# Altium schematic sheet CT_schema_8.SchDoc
size 368 x 245 mm
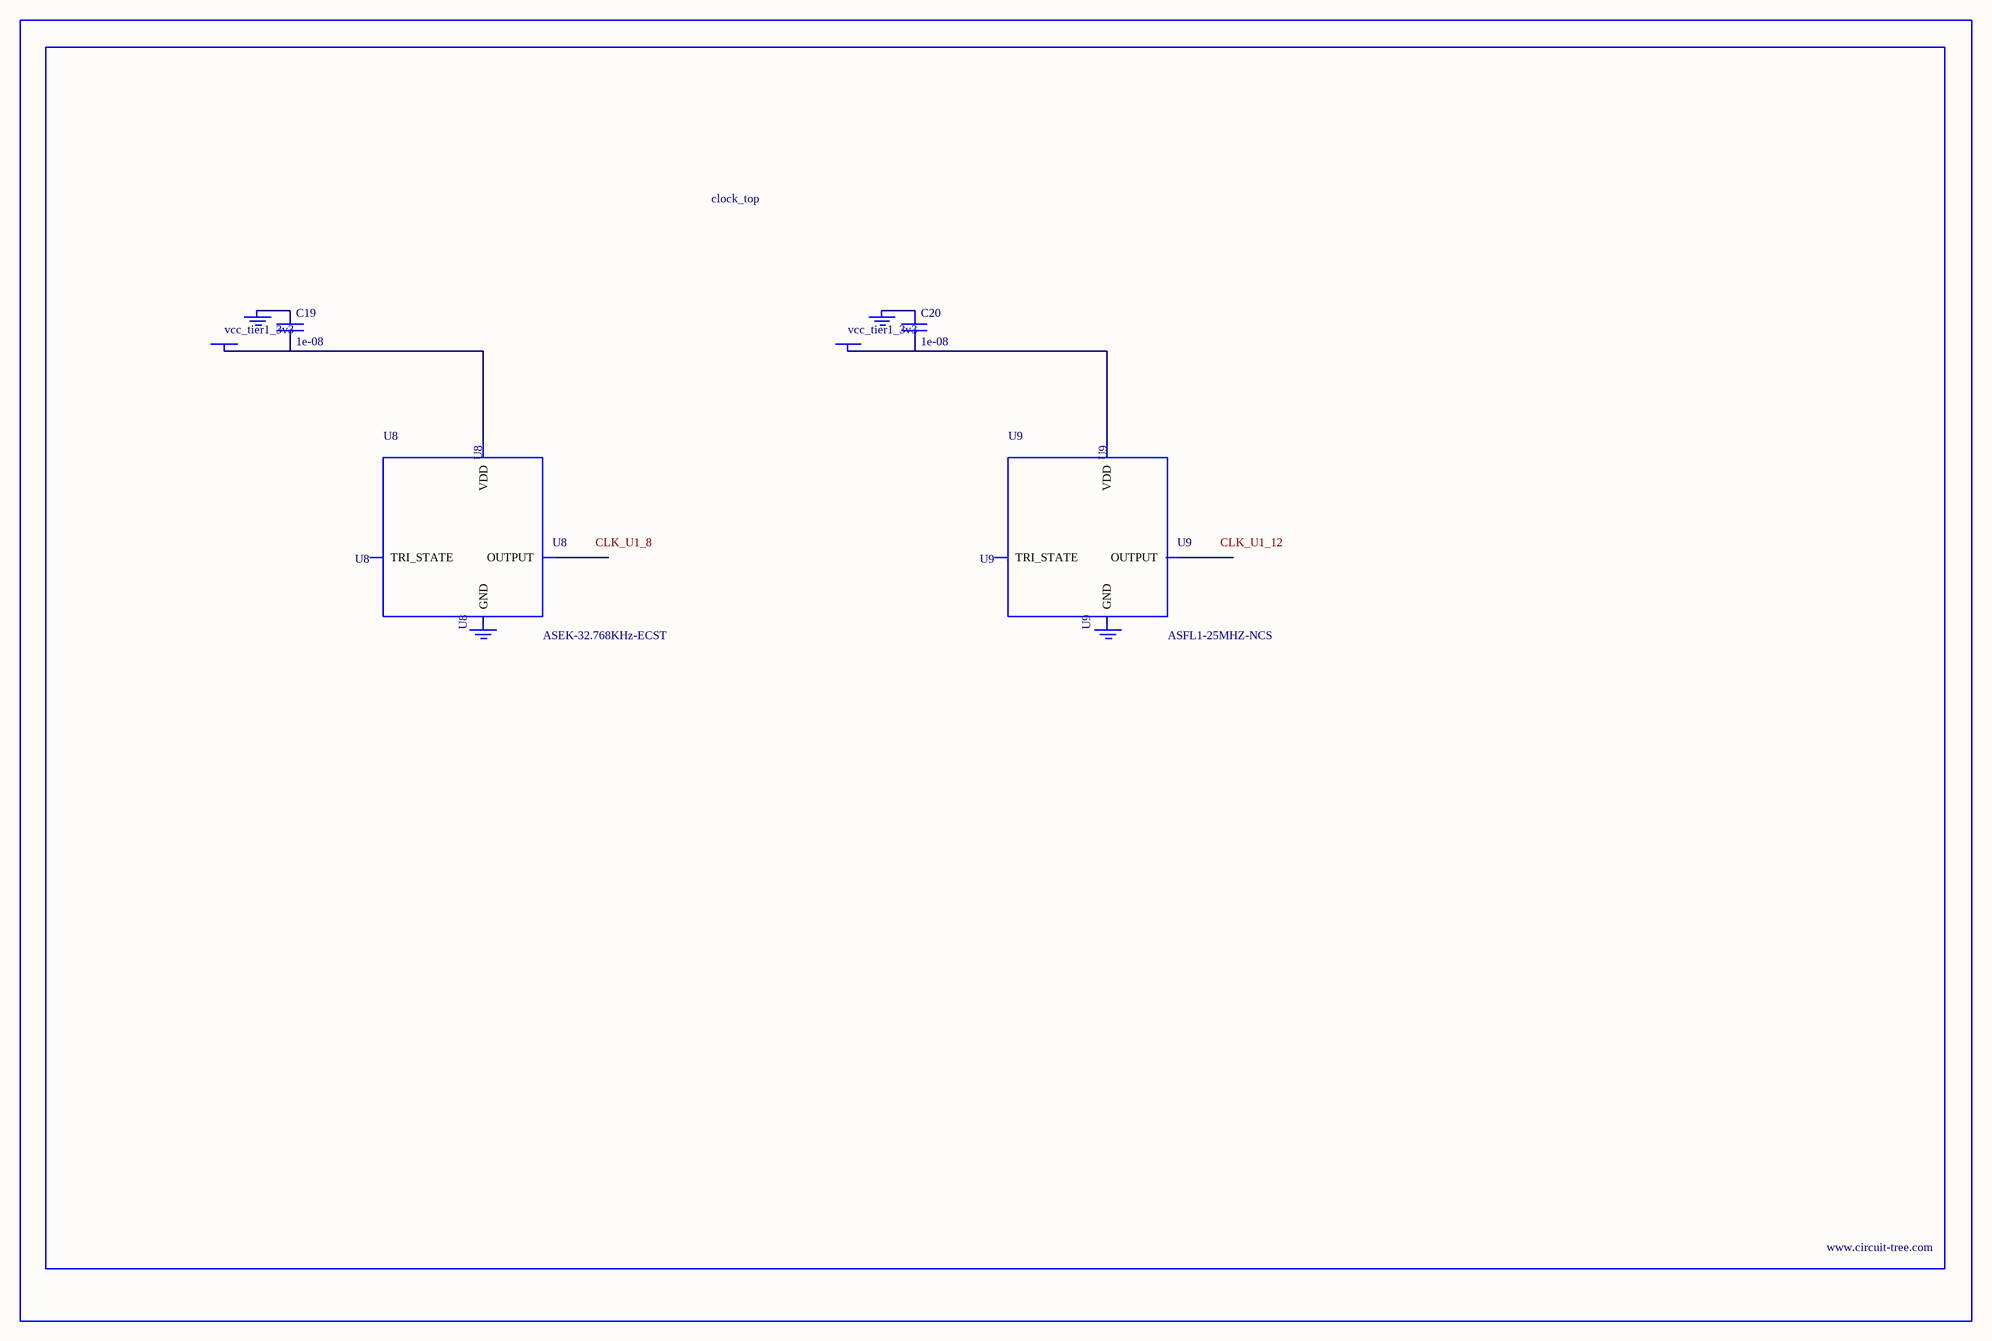
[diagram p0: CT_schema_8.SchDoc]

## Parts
BORDER7  (no value)
C19  1e-08  [C0402]
C20  1e-08  [C0402]
GND_INSTANCE_7_0  (no value)
GND_INSTANCE_7_1  (no value)
GND_INSTANCE_7_2  (no value)
GND_INSTANCE_7_3  (no value)
POWER_INSTANCE_7_0  vcc_tier1_3v3
POWER_INSTANCE_7_1  vcc_tier1_3v3
U8  ASEK-32.768KHz-ECST  [ASEK]
U9  ASFL1-25MHZ-NCS  [ASFL1]

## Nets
NetC19_1: C19.1 GND_INSTANCE_7_0.0(GND)
NetC19_2: C19.2 POWER_INSTANCE_7_0.0(PWR) U8.4(VDD)
NetC20_1: C20.1 GND_INSTANCE_7_2.0(GND)
NetC20_2: C20.2 POWER_INSTANCE_7_1.0(PWR) U9.4(VDD)

Not connected (* = marked no-connect by the designer): GND_INSTANCE_7_1 0(GND); GND_INSTANCE_7_3 0(GND); U8 1(TRI_STATE) 2(GND) 3(OUTPUT); U9 1(TRI_STATE) 2(GND) 3(OUTPUT)

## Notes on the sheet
- Labels drawn without touching a wire or pin: CLK_U1_8, CLK_U1_12

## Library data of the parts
BORDER7 = BORDER_PAGE7
C19 C20 = C0402C103K3RAC
GND_INSTANCE_7_0-GND_INSTANCE_7_3 = GND
POWER_INSTANCE_7_0 POWER_INSTANCE_7_1 = PWR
